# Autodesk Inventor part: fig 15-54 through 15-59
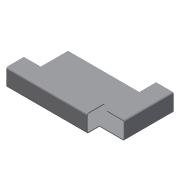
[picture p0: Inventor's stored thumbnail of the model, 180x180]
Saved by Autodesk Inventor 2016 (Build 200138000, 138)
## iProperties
Created: 2008-06
Part Number: fig 15-54 through 15-59
Material: Generic
Document SubType Name: Sheet Metal
Designer: CADCIM
Density: 1 g/cm^3
Sheet Metal Rule: Default_mm
Appearance: Default
Author: CADCIM
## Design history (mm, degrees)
node "Face1"
  sketch "Sketch1"
    geometry: L1 (-32.219, 35.011)-(27.554, 35.011); L2 (27.554, 35.011)-(27.554, 7.255); L3 (13.281, 0.063)-(-32.219, 0.063); L4 (-32.219, 0.063)-(-32.219, 35.011); L5 (13.281, 0.063)-(13.281, 7.255); L6 (13.281, 7.255)-(27.554, 7.255)
    constraints: 12 end point, 2 parallel, 2 perpendicular, 1 horizontal, 1 vertical
node "Flange5"
node "Flange6"
node "Flange7"
node "Flange8"
body "Solid1"
face "Plate1" dims "Thickness" = 0.5
sketch "Sketch6"
  geometry: L1 through (-22.75, 0) direction (1, 0); L2 through (0, 5) direction (0, 1); L3 (0, 10)-(-45.501, 10); L4 (-45.501, 10)-(-45.501, 0)
  constraints: 6 end point, 1 horizontal, 1 perpendicular, 1 vertical
face "Plate6" dims "d50" = 0.5 (= BendReliefWidth), "d51" = 0.25 (= BendReliefDepth), "d52" = 1 (= MinimumRemnant), "d53" = 0.5 (= BendRadius), "d54" = 10, "d55" = 90 deg, "d56" = 0.5 (= BendRadius), "d57" = 2 (= CornerReliefSize), "d58" = 0.5 (= GapSize), "d59" = 0.5 (= JacobiRadiusSize), "SeamGap" = 0.01, "Thickness" = 0.5
bend "Bend5" dims "d50" = 0.5 (= BendReliefWidth), "d51" = 0.25 (= BendReliefDepth), "d52" = 1 (= MinimumRemnant), "d53" = 0.5 (= BendRadius), "d54" = 10, "d55" = 90 deg, "d56" = 0.5 (= BendRadius), "SeamGap" = 0.01, "Thickness" = 0.5
feature "Corner5" dims "d54" = 10, "d55" = 90 deg, "d57" = 2 (= CornerReliefSize), "d58" = 0.5 (= GapSize), "d59" = 0.5 (= JacobiRadiusSize)
sketch "Sketch7"
  geometry: L1 through (-22.75, 0) direction (1, 1.64e-48); L2 through (0, 5) direction (-1.62e-48, 1); L3 (0, 10)-(-45.501, 10); L4 (-45.501, 10)-(-45.501, 0)
  constraints: 6 end point, 1 horizontal, 1 perpendicular, 1 vertical
face "Plate7" dims "d60" = 0.5 (= BendReliefWidth), "d61" = 0.25 (= BendReliefDepth), "d62" = 1 (= MinimumRemnant), "d63" = 0.5 (= BendRadius), "d64" = 10, "d65" = 90 deg, "d66" = 0.5 (= BendRadius), "d67" = 2 (= CornerReliefSize), "d68" = 0.5 (= GapSize), "d69" = 0.5 (= JacobiRadiusSize), "SeamGap" = 0.01, "Thickness" = 0.5
bend "Bend6" dims "d60" = 0.5 (= BendReliefWidth), "d61" = 0.25 (= BendReliefDepth), "d62" = 1 (= MinimumRemnant), "d63" = 0.5 (= BendRadius), "d64" = 10, "d65" = 90 deg, "d66" = 0.5 (= BendRadius), "SeamGap" = 0.01, "Thickness" = 0.5
feature "Corner6" dims "d64" = 10, "d65" = 90 deg, "d67" = 2 (= CornerReliefSize), "d68" = 0.5 (= GapSize), "d69" = 0.5 (= JacobiRadiusSize)
sketch "Sketch8"
  geometry: L1 through (-13.878, 0) direction (1, 0); L2 through (0, 5) direction (0, 1); L3 (0, 10)-(-27.756, 10); L4 (-27.756, 10)-(-27.756, 0)
  constraints: 6 end point, 1 horizontal, 1 perpendicular, 1 vertical
face "Plate8" dims "d70" = 0.5 (= BendReliefWidth), "d71" = 0.25 (= BendReliefDepth), "d72" = 1 (= MinimumRemnant), "d73" = 0.5 (= BendRadius), "d74" = 10, "d75" = 90 deg, "d76" = 0.5 (= BendRadius), "d77" = 2 (= CornerReliefSize), "d78" = 0.5 (= GapSize), "d79" = 0.5 (= JacobiRadiusSize), "SeamGap" = 0.01, "Thickness" = 0.5
bend "Bend7" dims "d70" = 0.5 (= BendReliefWidth), "d71" = 0.25 (= BendReliefDepth), "d72" = 1 (= MinimumRemnant), "d73" = 0.5 (= BendRadius), "d74" = 10, "d75" = 90 deg, "d76" = 0.5 (= BendRadius), "SeamGap" = 0.01, "Thickness" = 0.5
feature "Corner7" dims "d74" = 10, "d75" = 90 deg, "d77" = 2 (= CornerReliefSize), "d78" = 0.5 (= GapSize), "d79" = 0.5 (= JacobiRadiusSize)
sketch "Sketch9"
  geometry: L1 through (0, -13.878) direction (-0, 1); L2 through (-5, 0) direction (-1, 4.3e-35); L3 (-10, 0)-(-10, -27.756); L4 (-10, -27.756)-(0, -27.756)
  constraints: 6 end point, 1 horizontal, 1 perpendicular, 1 vertical
face "Plate9" dims "d80" = 0.5 (= BendReliefWidth), "d81" = 0.25 (= BendReliefDepth), "d82" = 1 (= MinimumRemnant), "d83" = 0.5 (= BendRadius), "d84" = 10, "d85" = 90 deg, "d86" = 0.5 (= BendRadius), "d87" = 2 (= CornerReliefSize), "d88" = 0.5 (= GapSize), "d89" = 0.5 (= JacobiRadiusSize), "SeamGap" = 0.01, "Thickness" = 0.5
bend "Bend8" dims "d80" = 0.5 (= BendReliefWidth), "d81" = 0.25 (= BendReliefDepth), "d82" = 1 (= MinimumRemnant), "d83" = 0.5 (= BendRadius), "d84" = 10, "d85" = 90 deg, "d86" = 0.5 (= BendRadius), "SeamGap" = 0.01, "Thickness" = 0.5
feature "Corner8" dims "d84" = 10, "d85" = 90 deg, "d87" = 2 (= CornerReliefSize), "d88" = 0.5 (= GapSize), "d89" = 0.5 (= JacobiRadiusSize)
other parameters: "BendRadius" = 0.5 (= Thickness), "BendReliefWidth" = 0.5 (= Thickness), "BendReliefDepth" = 0.25 (= 0.5 x Thickness), "CornerReliefSize" = 2 (= 4 x Thickness), "MinimumRemnant" = 1 (= 2 x Thickness), "TransitionRadius" = 0.5 (= BendRadius), "JacobiRadiusSize" = 0.5 (= BendRadius), "d0" = 0.5 (= BendRadius), "GapSize" = 0.5 (= Thickness)
